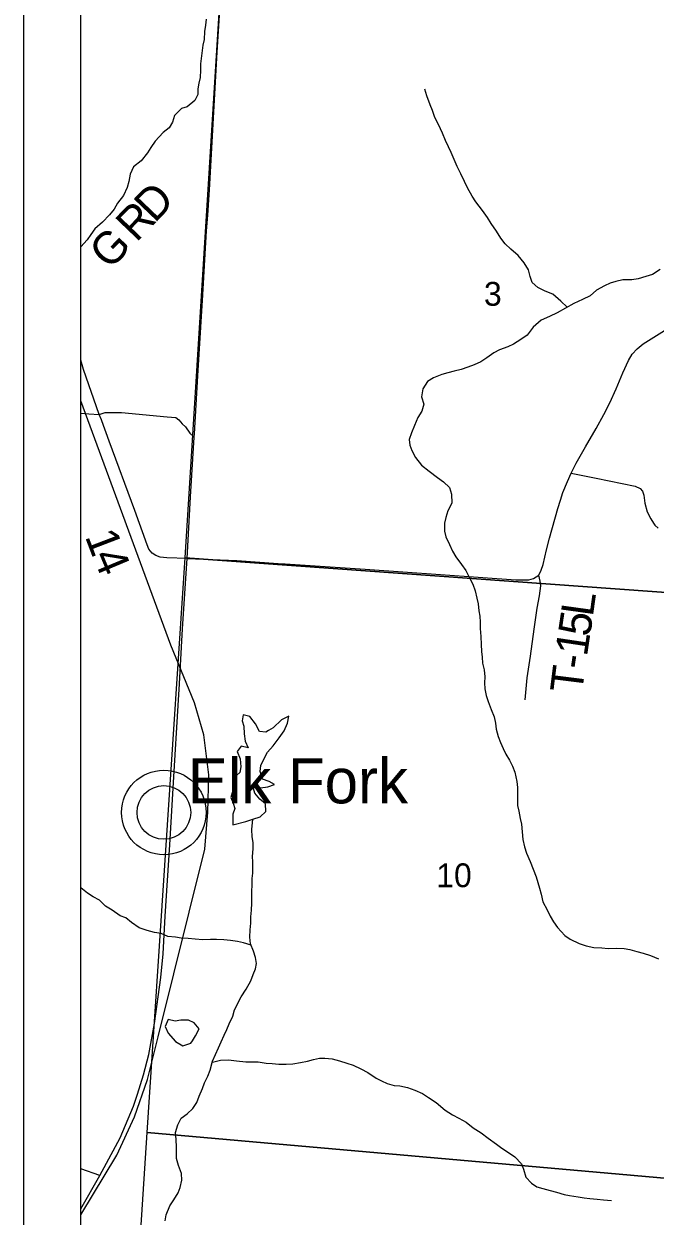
# Model space of a CAD drawing. Extents: x 0 to 34, y 0 to 22.
# Drawn here: x 23.417 to 24.527, y 16.992 to 19.088 of the extents above; entities that cross this region are included whole.
import ezdxf

# ---------------------------------------------------------------- set-up
doc = ezdxf.new("R2010")
doc.units = 0
for name, color, linetype in [('GM_X_County_Road', 7, 'Continuous'), ('GM_X_County_Road_Text', 7, 'Continuous'), ('GM_X_Minor_Lake', 7, 'Continuous'), ('GM_X_Minor_River', 7, 'Continuous'), ('GM_X_Rail_Line', 7, 'Continuous'), ('GM_X_Section', 7, 'Continuous'), ('GM_X_Section_Text', 7, 'Continuous'), ('GM_X_State_Route', 7, 'Continuous'), ('GM_X_Township_Road', 7, 'Continuous'), ('GM_X_Township_Road_Text', 7, 'Continuous'), ('GM_X_Unincorporated', 7, 'Continuous'), ('GM_X_Unincorporated_Location', 7, 'Continuous'), ('GM_X_Unincorporated_Text', 7, 'Continuous'), ('SH_Data', 7, 'Continuous')]:
    doc.layers.add(name, color=color, linetype=linetype)

msp = doc.modelspace()

# ---------------------------------------------------------------- linework, layer by layer
at = {"layer": 'GM_X_County_Road'}
msp.add_line((23.5501, 17.0628), (23.5167, 17.0746), dxfattribs=at)
for points in [[(23.5532, 18.3919), (23.5491, 18.4013), (23.5218, 18.4806), (23.5167, 18.4969)], [(23.7042, 18.1483), (23.6682, 18.1491), (23.6563, 18.1506), (23.6489, 18.1534), (23.6425, 18.1576), (23.6366, 18.1648), (23.6339, 18.172), (23.6122, 18.2326), (23.5669, 18.3545), (23.554, 18.3901), (23.5532, 18.3919)]]:
    msp.add_lwpolyline(points, dxfattribs=at)
at = {"layer": 'GM_X_Minor_Lake'}
for points in [[(23.8471, 17.8455), (23.8424, 17.8427), (23.831, 17.8438), (23.8241, 17.8575), (23.8143, 17.8703), (23.8025, 17.873), (23.801, 17.8627), (23.8037, 17.8532), (23.8045, 17.84), (23.8061, 17.8271), (23.8114, 17.815), (23.7989, 17.818), (23.7917, 17.8085), (23.7971, 17.7956), (23.7983, 17.7816), (23.7968, 17.7717), (23.7862, 17.7626), (23.7859, 17.7497), (23.7844, 17.7402), (23.781, 17.7277), (23.7849, 17.7178), (23.7879, 17.7084), (23.7842, 17.6985), (23.7843, 17.68)], [(23.7843, 17.68), (23.8069, 17.6856), (23.8194, 17.6898), (23.8322, 17.6937), (23.8424, 17.7032), (23.8416, 17.7168), (23.8318, 17.7248), (23.823, 17.7357), (23.8203, 17.7452), (23.8332, 17.7449), (23.8457, 17.7464), (23.8578, 17.7506), (23.8483, 17.7559), (23.8362, 17.76), (23.8324, 17.7737), (23.8335, 17.7839), (23.8395, 17.7964), (23.8455, 17.8075), (23.8553, 17.8189), (23.8659, 17.8325), (23.8745, 17.8451), (23.8805, 17.8587), (23.8828, 17.8709), (23.8699, 17.8644), (23.8552, 17.8503), (23.8471, 17.8455)], [(23.6703, 17.3372), (23.665, 17.3251), (23.6707, 17.3133), (23.6832, 17.2989), (23.6961, 17.291), (23.7105, 17.2956), (23.7131, 17.2997)], [(23.7131, 17.2997), (23.7188, 17.3089), (23.7248, 17.321), (23.7165, 17.3313), (23.7062, 17.3365), (23.693, 17.3365), (23.6831, 17.3346), (23.6703, 17.3372)]]:
    msp.add_lwpolyline(points, dxfattribs=at)
at = {"layer": 'GM_X_Minor_River'}
for points in [[(23.7376, 19.0967), (23.7361, 19.0861), (23.7347, 19.0747), (23.7336, 19.0611), (23.7317, 19.0508), (23.7302, 19.0414), (23.7288, 19.0277), (23.7276, 19.0182), (23.7273, 19.0068), (23.727, 18.994), (23.7247, 18.9841), (23.7229, 18.9739), (23.7229, 18.9644), (23.7173, 18.9537), (23.704, 18.9427), (23.6938, 18.9397), (23.6814, 18.9271), (23.6784, 18.9157), (23.6724, 18.9055), (23.6618, 18.8975), (23.6475, 18.8823), (23.6403, 18.8709), (23.6343, 18.8614), (23.623, 18.8477), (23.6094, 18.8371), (23.6037, 18.8238), (23.6011, 18.8113), (23.5985, 18.8003), (23.5921, 18.7866), (23.5816, 18.7729), (23.5755, 18.7623), (23.5672, 18.7524), (23.5548, 18.7395), (23.5416, 18.7281), (23.5344, 18.7182), (23.528, 18.7084), (23.5167, 18.6963)], [(24.3727, 18.5901), (24.3612, 18.6004), (24.3471, 18.6129), (24.3335, 18.6182), (24.3206, 18.6246), (24.3111, 18.6337), (24.3073, 18.6443), (24.3046, 18.6556), (24.297, 18.6681), (24.286, 18.681), (24.2734, 18.692), (24.2636, 18.7014), (24.2556, 18.7116), (24.2483, 18.7238), (24.2388, 18.737), (24.232, 18.748), (24.2236, 18.7601), (24.2115, 18.7752), (24.2054, 18.7855), (24.197, 18.8002), (24.1917, 18.8112), (24.1852, 18.8248), (24.1791, 18.8373), (24.1734, 18.8498), (24.1684, 18.8619), (24.1634, 18.8722), (24.1585, 18.8835), (24.1531, 18.896), (24.1459, 18.9116), (24.1398, 18.9237), (24.1356, 18.9358), (24.1314, 18.946), (24.1257, 18.9616), (24.1222, 18.9737)], [(24.5362, 18.6566), (24.5223, 18.6478), (24.5109, 18.644), (24.4973, 18.6402), (24.4863, 18.6379), (24.4701, 18.6382), (24.4583, 18.6352), (24.4481, 18.6321), (24.4379, 18.6279), (24.4239, 18.6199), (24.4126, 18.61), (24.3994, 18.6036), (24.3843, 18.5967), (24.3695, 18.5883), (24.3548, 18.5803), (24.3416, 18.5735), (24.3264, 18.567), (24.3129, 18.5548), (24.3019, 18.5411), (24.291, 18.5331), (24.2781, 18.5248), (24.2683, 18.5206), (24.2536, 18.5149), (24.2437, 18.5099), (24.2309, 18.5008), (24.2207, 18.4939), (24.209, 18.4886), (24.1976, 18.4844), (24.1859, 18.4806), (24.1738, 18.4775), (24.1628, 18.4748), (24.1519, 18.4718)], [(24.1519, 18.4718), (24.1371, 18.466), (24.1269, 18.4596), (24.1186, 18.4467), (24.1164, 18.4326), (24.1202, 18.4197), (24.1165, 18.4072), (24.1097, 18.3958), (24.1037, 18.3818), (24.0984, 18.3693), (24.0947, 18.3571), (24.0955, 18.3476), (24.0989, 18.3378), (24.1054, 18.3257), (24.1164, 18.3124), (24.1297, 18.3018), (24.1445, 18.2905), (24.1547, 18.2829), (24.1654, 18.2731), (24.1692, 18.2614), (24.1696, 18.2454), (24.1625, 18.2322), (24.1591, 18.22), (24.1569, 18.2101), (24.1569, 18.1961), (24.1592, 18.1863), (24.1653, 18.1726), (24.1707, 18.1613), (24.1764, 18.151), (24.1863, 18.1378), (24.1942, 18.1268), (24.1996, 18.1162), (24.2064, 18.103), (24.2106, 18.0912), (24.2137, 18.0783), (24.2156, 18.0685), (24.2168, 18.0563), (24.2187, 18.0469), (24.2195, 18.0359), (24.2192, 18.0249), (24.2207, 18.0112), (24.2212, 17.9968), (24.2216, 17.9847), (24.2227, 17.9748), (24.2235, 17.9642), (24.2262, 17.9521), (24.2278, 17.9403), (24.2271, 17.9297), (24.2278, 17.9191), (24.2302, 17.9074), (24.2332, 17.8968), (24.2389, 17.8827), (24.2439, 17.8695), (24.2462, 17.8585), (24.2478, 17.8479), (24.2512, 17.835), (24.2554, 17.8244), (24.26, 17.8142), (24.2646, 17.8043), (24.2707, 17.7937), (24.2764, 17.7827), (24.2802, 17.7725), (24.284, 17.7562), (24.2852, 17.7452), (24.2852, 17.735), (24.2849, 17.7247), (24.2849, 17.7137), (24.2872, 17.7035), (24.2899, 17.691), (24.2922, 17.6808), (24.2946, 17.6542), (24.2973, 17.6413), (24.3011, 17.63), (24.3072, 17.6152), (24.3125, 17.6019), (24.3179, 17.5883), (24.324, 17.5686), (24.3267, 17.558), (24.3298, 17.5443), (24.3374, 17.5303), (24.3427, 17.5193), (24.3484, 17.5091), (24.3553, 17.4989), (24.3682, 17.4853), (24.3777, 17.4785), (24.3936, 17.4709), (24.4061, 17.4672), (24.4194, 17.4642), (24.4337, 17.4634), (24.4447, 17.4623), (24.4587, 17.4628), (24.4727, 17.462), (24.4826, 17.4602), (24.4951, 17.4572), (24.5061, 17.4541), (24.5193, 17.45), (24.533, 17.444)], [(23.8196, 17.6148), (23.8188, 17.6242), (23.8203, 17.6375), (23.8199, 17.6489), (23.8184, 17.6588), (23.8179, 17.6713), (23.8194, 17.6898)], [(23.665, 16.9834), (23.6668, 16.994), (23.6736, 17.0096), (23.6807, 17.0202), (23.6883, 17.0328), (23.6917, 17.0422), (23.6946, 17.0548), (23.6942, 17.0665), (23.6889, 17.0805), (23.6851, 17.0927), (23.685, 17.1021), (23.6854, 17.1131), (23.6849, 17.1264), (23.6834, 17.1389), (23.6875, 17.1522), (23.6935, 17.1636), (23.7037, 17.1712), (23.7139, 17.1807), (23.7211, 17.1913), (23.7252, 17.2027), (23.7312, 17.216), (23.7346, 17.2259), (23.7406, 17.238), (23.7447, 17.2483), (23.7488, 17.2642), (23.7541, 17.276), (23.759, 17.2878), (23.7639, 17.298), (23.7691, 17.3098), (23.774, 17.32), (23.7778, 17.3299), (23.7842, 17.3432), (23.7875, 17.3542), (23.7988, 17.377), (23.8079, 17.391), (23.8161, 17.4054), (23.8203, 17.4168), (23.824, 17.4263), (23.8259, 17.4358), (23.8243, 17.4464), (23.8205, 17.4578), (23.8152, 17.4707), (23.814, 17.482), (23.8147, 17.4953), (23.8158, 17.5067), (23.8162, 17.5177), (23.8173, 17.5294), (23.8176, 17.542), (23.8176, 17.5526), (23.8179, 17.5624), (23.8183, 17.5742), (23.8186, 17.5856), (23.8193, 17.595), (23.8197, 17.6053), (23.8196, 17.6148)], [(23.8163, 17.4679), (23.8031, 17.4721), (23.7928, 17.4748), (23.7803, 17.4763), (23.7686, 17.4774), (23.7553, 17.4781), (23.7451, 17.4781), (23.7315, 17.4773), (23.7182, 17.4784), (23.7058, 17.4799), (23.6936, 17.4802), (23.6834, 17.4821), (23.6698, 17.4836), (23.658, 17.4885), (23.6467, 17.4903), (23.6338, 17.4941), (23.6198, 17.4986), (23.6061, 17.5077), (23.5959, 17.516), (23.5864, 17.5198), (23.5723, 17.5296), (23.5606, 17.5368), (23.5496, 17.547), (23.5386, 17.553), (23.5287, 17.5598), (23.5167, 17.5688)], [(23.7483, 17.2621), (23.7625, 17.2661), (23.7769, 17.2662), (23.7909, 17.2647), (23.8071, 17.2632), (23.8174, 17.2629), (23.8287, 17.2629), (23.8431, 17.2607), (23.8537, 17.2599), (23.8655, 17.2588), (23.8783, 17.2588), (23.8901, 17.2593), (23.9033, 17.2616), (23.9154, 17.2642), (23.926, 17.2669), (23.9366, 17.2692), (23.9464, 17.2696), (23.9593, 17.2685), (23.9718, 17.2648), (23.9847, 17.2606), (23.9961, 17.2569), (24.0093, 17.2508), (24.0218, 17.244), (24.0366, 17.2342), (24.0461, 17.2297), (24.0556, 17.2248), (24.0681, 17.2214), (24.0783, 17.2207), (24.0916, 17.218), (24.1045, 17.2131), (24.1177, 17.2075), (24.1287, 17.2003), (24.142, 17.1912), (24.158, 17.178), (24.1705, 17.1697), (24.1818, 17.164), (24.1947, 17.1569), (24.2073, 17.147), (24.2213, 17.1383), (24.2334, 17.1285), (24.2479, 17.1179), (24.2573, 17.1111), (24.2672, 17.1047), (24.2805, 17.0956), (24.2923, 17.0835), (24.2957, 17.0741), (24.2995, 17.06), (24.3098, 17.0494), (24.3193, 17.0434), (24.3295, 17.0404), (24.3424, 17.0366), (24.3537, 17.034), (24.367, 17.0299), (24.3765, 17.028), (24.3916, 17.0254), (24.4022, 17.0235), (24.4125, 17.0224), (24.425, 17.0213), (24.4363, 17.0202), (24.4503, 17.0191)]]:
    msp.add_lwpolyline(points, dxfattribs=at)
at = {"layer": 'GM_X_Rail_Line'}
msp.add_lwpolyline([(23.5167, 16.9936), (23.5804, 17.0986), (23.6113, 17.1665), (23.6343, 17.2317), (23.6529, 17.3068), (23.7348, 17.6372), (23.7406, 17.7022), (23.7419, 17.7675), (23.7335, 17.8381), (23.7167, 17.8942), (23.6755, 17.9955), (23.5167, 18.4251)], dxfattribs=at)
at = {"layer": 'GM_X_Section'}
for points in [[(23.7643, 19.174), (23.7939, 19.171), (24.788, 19.1066), (24.7175, 18.0761), (23.7006, 18.1492)], [(23.7006, 18.1492), (24.7175, 18.0761), (24.6497, 17.049), (23.6339, 17.1388)], [(24.6497, 17.049), (24.5822, 16.0431), (23.5665, 16.1079), (23.6339, 17.1388)]]:
    msp.add_lwpolyline(points, close=True, dxfattribs=at)
at = {"layer": 'GM_X_State_Route'}
for points in [[(23.7042, 18.1483), (23.71, 18.2567), (23.7163, 18.3616), (23.7166, 18.3673), (23.7229, 18.4696), (23.7282, 18.5549), (23.7307, 18.6019), (23.7382, 18.7246), (23.7401, 18.752), (23.743, 18.7962), (23.7497, 18.9118), (23.7506, 18.9339), (23.7569, 19.0384), (23.7617, 19.1125), (23.7675, 19.1733), (23.7785, 19.2701), (23.7909, 19.3586), (23.8012, 19.4381)], [(23.8641, 18.1394), (23.8761, 18.1385), (24.017, 18.1292), (24.0835, 18.1248), (24.2821, 18.1108), (24.2954, 18.1104), (24.305, 18.1104), (24.3132, 18.1129), (24.3226, 18.1188), (24.3264, 18.1277), (24.33, 18.1373), (24.3359, 18.1634), (24.3412, 18.1838), (24.3562, 18.2363), (24.3609, 18.2507), (24.3649, 18.2639), (24.3728, 18.2838), (24.3797, 18.2982), (24.388, 18.3157), (24.4048, 18.3444), (24.4237, 18.377), (24.4372, 18.4012), (24.4472, 18.4216), (24.4586, 18.4465), (24.4702, 18.4747), (24.4803, 18.4961), (24.4868, 18.5073), (24.4953, 18.5171), (24.5064, 18.5256), (24.5436, 18.5492)], [(23.5781, 17.1143), (23.5861, 17.129), (23.6097, 17.1851), (23.6165, 17.2059), (23.627, 17.2401), (23.6365, 17.2757), (23.6463, 17.3301), (23.6578, 17.4111), (23.6618, 17.4526), (23.6655, 17.5189), (23.6733, 17.6448), (23.6806, 17.7643), (23.6879, 17.8897), (23.6904, 17.9278), (23.696, 18.0245), (23.7042, 18.1483)], [(23.7042, 18.1483), (23.7913, 18.1445), (23.8641, 18.1394)], [(23.5167, 17.0047), (23.5501, 17.0628), (23.5781, 17.1143)]]:
    msp.add_lwpolyline(points, dxfattribs=at)
at = {"layer": 'GM_X_Township_Road'}
for points in [[(23.5167, 18.4036), (23.5311, 18.4026), (23.5491, 18.4013)], [(23.5491, 18.4013), (23.5595, 18.4051), (23.5883, 18.4049), (23.6688, 18.3971), (23.6843, 18.3958), (23.6894, 18.392), (23.6951, 18.3852), (23.701, 18.3797), (23.7089, 18.3685), (23.7163, 18.3616)], [(24.3797, 18.2982), (24.4235, 18.2891), (24.4919, 18.2754), (24.501, 18.2712), (24.5048, 18.2666), (24.5074, 18.2593), (24.5092, 18.2456), (24.513, 18.2299), (24.5195, 18.2176), (24.5242, 18.2102)], [(24.5242, 18.2102), (24.5265, 18.2065), (24.5327, 18.2015)], [(24.2986, 17.8997), (24.3022, 17.9383), (24.3077, 17.9762), (24.3143, 18.0241), (24.3198, 18.0606), (24.3236, 18.0822), (24.3262, 18.1002), (24.3251, 18.1085), (24.3226, 18.1188)]]:
    msp.add_lwpolyline(points, dxfattribs=at)
at = {"layer": 'GM_X_Unincorporated'}
for radius in [0.0744, 0.0472]:
    msp.add_circle((23.663, 17.7015), radius, dxfattribs=at)
at = {"layer": 'GM_X_Unincorporated_Location'}
msp.add_line((23.663, 17.7015), (23.663, 17.7015), dxfattribs=at)
at = {"layer": 'SH_Data'}
for points in [[(23.4167, 21), (30.4167, 21), (30.4167, 14), (23.4167, 14)], [(23.5167, 20.9), (30.3167, 20.9), (30.3167, 14.1), (23.5167, 14.1)]]:
    msp.add_lwpolyline(points, close=True, dxfattribs=at)

# ---------------------------------------------------------------- texts
at = {"layer": 'GM_X_County_Road_Text'}
for s, rotation, p in [('D', 46.3054, (23.6468, 18.7367)), ('R', 46.3059, (23.6145, 18.703)), ('G', 46.3035, (23.5679, 18.6542)), ('1', 290.8712, (23.5237, 18.1871)), ('4', 292.7486, (23.5369, 18.1526))]:
    msp.add_text(s, height=0.0568, rotation=rotation, dxfattribs=at).set_placement(p)
at = {"layer": 'GM_X_Section_Text'}
for s, height, p in [('3', 0.0419, (24.2261, 18.5926)), ('10', 0.04186, (24.1423, 17.5701))]:
    msp.add_text(s, height=height, rotation=0, dxfattribs=at).set_placement(p)
at = {"layer": 'GM_X_Township_Road_Text'}
for s, rotation, p in [('L', 82.1031, (24.4175, 18.0444)), ('5', 81.4718, (24.4123, 18.0091)), ('1', 81.4651, (24.4071, 17.9745)), ('-', 81.5862, (24.4036, 17.9514)), ('T', 82.9281, (24.3985, 17.9096))]:
    msp.add_text(s, height=0.0568, rotation=rotation, dxfattribs=at).set_placement(p)
at = {"layer": 'GM_X_Unincorporated_Text'}
msp.add_text('Elk Fork', height=0.07898, rotation=0, dxfattribs=at).set_placement((23.7052, 17.7175))

doc.saveas('drawing.dxf')
